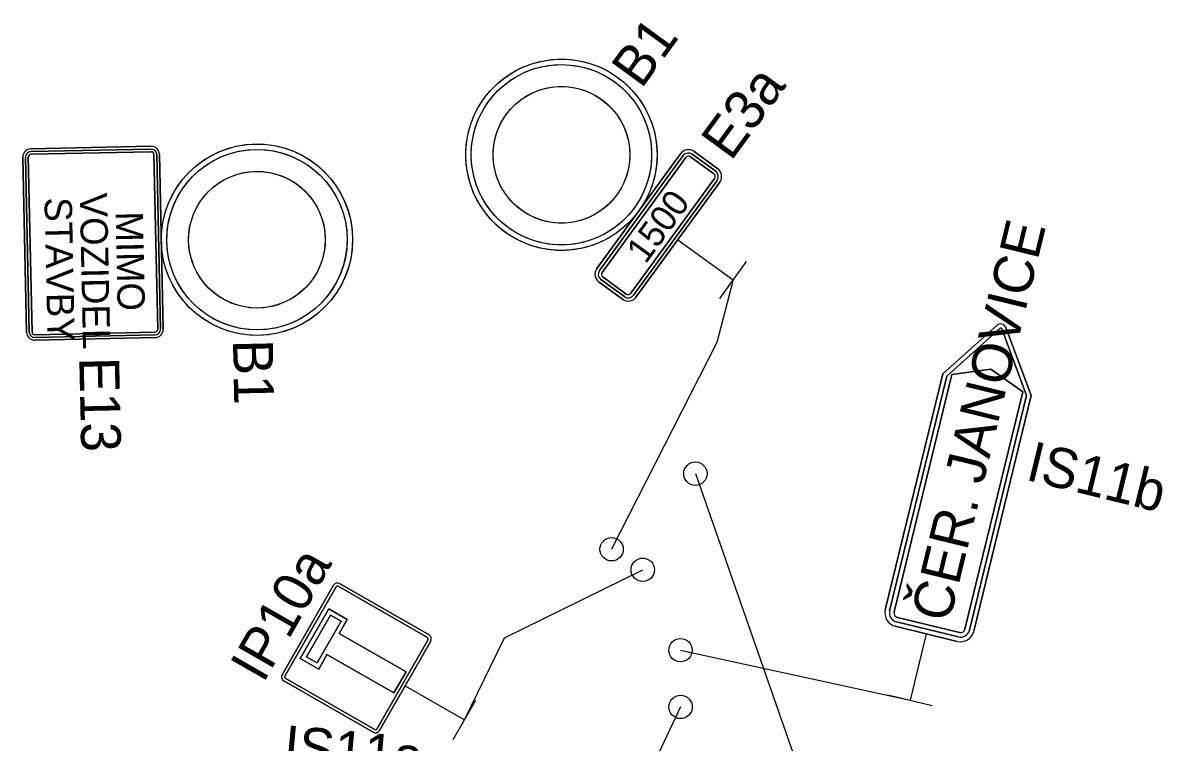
# Model space of a CAD drawing. Extents: x -688893 to -679983, y -1088371 to -1075771.
# Drawn here: x -685301 to -683799, y -1081610 to -1080663 of the extents above; entities that cross this region are included whole.
import ezdxf

# ---------------------------------------------------------------- set-up
doc = ezdxf.new("R2010")
doc.units = 0
for name, color, linetype in [('SDZ', 7, 'Continuous'), ('SDZ ozn', 7, 'Continuous'), ('SDZ plochy', 7, 'Continuous'), ('SDZ symbol', 7, 'Continuous'), ('SDZ text', 7, 'Continuous')]:
    doc.layers.add(name, color=color, linetype=linetype)

msp = doc.modelspace()

# ---------------------------------------------------------------- linework, layer by layer
at = {"layer": 'SDZ'}
for p, q in [((-685290.3, -1080828.6), (-685131.9, -1080825.2)), ((-685290.3, -1080828.6), (-685290.3, -1080828.6)), ((-685290.2, -1080832.2), (-685131.8, -1080828.8)), ((-685295.9, -1081069.9), (-685300.8, -1080839.6)), ((-685292.3, -1081069.8), (-685297.2, -1080839.5)), ((-685293.6, -1080839.4), (-685288.7, -1081069.8)), ((-685131.8, -1080832.4), (-685290.1, -1080835.8)), ((-685123.2, -1081066.2), (-685128.1, -1080835.9)), ((-685124.5, -1080835.8), (-685119.6, -1081066.2)), ((-685120.9, -1080835.7), (-685116, -1081066.1)), ((-684438.2, -1080948.2), (-684365.5, -1081001.2)), ((-684383.2, -1081025.5), (-684347.8, -1080977)), ((-685285, -1081073.3), (-685126.7, -1081069.9)), ((-684089.5, -1081124.8), (-684018.3, -1081061.1)), ((-684014.1, -1081065), (-684084.1, -1081128)), ((-684018.4, -1081061.2), (-684018.4, -1081061.2)), ((-683979.2, -1081153.5), (-684011.7, -1081065.6)), ((-684006.3, -1081064), (-683972.9, -1081153.2)), ((-685126.6, -1081073.5), (-685285, -1081076.9)), ((-685126.5, -1081077.1), (-685284.9, -1081080.5)), ((-684165.2, -1081435.5), (-684089.5, -1081124.8)), ((-684084.1, -1081128), (-684159.4, -1081436.9)), ((-684153.5, -1081438.4), (-684077.4, -1081125.9)), ((-684077.4, -1081125.9), (-684026.2, -1081118.6)), ((-684026.2, -1081118.6), (-683984.2, -1081148.6)), ((-683984.2, -1081148.6), (-684060.3, -1081461.1)), ((-684054.4, -1081462.5), (-683979.2, -1081153.5)), ((-683972.9, -1081153.2), (-684048.6, -1081463.9)), ((-684415.2, -1081256.3), (-683939.8, -1082615.4)), ((-684959.3, -1081521.1), (-684891.8, -1081403.3)), ((-684959.3, -1081521.1), (-684891.8, -1081403.3)), ((-684955.9, -1081523.1), (-684888.3, -1081405.3)), ((-684955.9, -1081523.1), (-684888.3, -1081405.3)), ((-684885.7, -1081404.5), (-684767.8, -1081472.1)), ((-684885.7, -1081404.5), (-684767.8, -1081472.1)), ((-684883.7, -1081401.1), (-684765.9, -1081468.7)), ((-684883.7, -1081401.1), (-684765.9, -1081468.7)), ((-684935.4, -1081499.7), (-684898, -1081434.4)), ((-684935.4, -1081499.7), (-684898, -1081434.4)), ((-684927.4, -1081497.5), (-684895.8, -1081442.5)), ((-684927.4, -1081497.5), (-684895.8, -1081442.5)), ((-684898, -1081434.4), (-684873.8, -1081448.3)), ((-684898, -1081434.4), (-684873.8, -1081448.3)), ((-684895.8, -1081442.5), (-684881.8, -1081450.5)), ((-684895.8, -1081442.5), (-684881.8, -1081450.5)), ((-684881.8, -1081450.5), (-684913.4, -1081505.5)), ((-684881.8, -1081450.5), (-684913.4, -1081505.5)), ((-684873.8, -1081448.3), (-684884.3, -1081466.6)), ((-684873.8, -1081448.3), (-684884.3, -1081466.6)), ((-684070.4, -1081477.2), (-684152, -1081457.3)), ((-684150.6, -1081451.4), (-684068.9, -1081471.3)), ((-684067.5, -1081465.5), (-684149.1, -1081445.6)), ((-684884.3, -1081466.6), (-684796.1, -1081517.1)), ((-684884.3, -1081466.6), (-684796.1, -1081517.1)), ((-684767.1, -1081474.8), (-684834.7, -1081592.6)), ((-684767.1, -1081474.8), (-684834.7, -1081592.6)), ((-684111.2, -1081467.2), (-684132.5, -1081554.7)), ((-684763.7, -1081476.7), (-684831.2, -1081594.6)), ((-684763.7, -1081476.7), (-684831.2, -1081594.6)), ((-684911.2, -1081513.6), (-684935.4, -1081499.7)), ((-684911.2, -1081513.6), (-684935.4, -1081499.7)), ((-684913.4, -1081505.5), (-684927.4, -1081497.5)), ((-684913.4, -1081505.5), (-684927.4, -1081497.5)), ((-684900.3, -1081494.6), (-684911.2, -1081513.6)), ((-684900.3, -1081494.6), (-684911.2, -1081513.6)), ((-684812.2, -1081545.1), (-684900.3, -1081494.6)), ((-684812.2, -1081545.1), (-684900.3, -1081494.6)), ((-684796.1, -1081517.1), (-684812.2, -1081545.1)), ((-684796.1, -1081517.1), (-684812.2, -1081545.1)), ((-684839.3, -1081596.8), (-684957.1, -1081529.2)), ((-684839.3, -1081596.8), (-684957.1, -1081529.2)), ((-684837.3, -1081593.4), (-684955.2, -1081525.8)), ((-684837.3, -1081593.4), (-684955.2, -1081525.8)), ((-684797.5, -1081535.7), (-684719.4, -1081580.4)), ((-684161.6, -1081547.6), (-684103.3, -1081561.8)), ((-684734.3, -1081606.5), (-684704.5, -1081554.4))]:
    msp.add_line(p, q, dxfattribs=at)
for points in [[(-684544.9, -1080986.2), (-684434.6, -1080835)], [(-684541.5, -1080988.7), (-684431.2, -1080837.5)], [(-684538.1, -1080991.3), (-684427.7, -1080840)], [(-684421.8, -1080839), (-684390.8, -1080861.6)], [(-684419.3, -1080835.6), (-684388.3, -1080858.2)], [(-684416.8, -1080832.2), (-684385.8, -1080854.7)], [(-684389.9, -1080867.5), (-684500.2, -1081018.8)], [(-684386.5, -1080870.1), (-684496.8, -1081021.3)], [(-684383, -1080872.6), (-684493.4, -1081023.9)], [(-684511.2, -1081026.6), (-684542.1, -1081004.1)], [(-684508.7, -1081023.2), (-684539.6, -1081000.6)], [(-684506.2, -1081019.8), (-684537.1, -1080997.2)], [(-684365.5, -1081001.2), (-684386.9, -1081083.8), (-684525.5, -1081355.9)], [(-684719.4, -1081580.4), (-684666.5, -1081472.6), (-684484.5, -1081382.9)], [(-684434.8, -1081488.7), (-684132.5, -1081554.7)], [(-684434.7, -1081563.5), (-684738.1, -1082207.5), (-684913.1, -1082202.6)]]:
    msp.add_lwpolyline(points, dxfattribs=at)
for centre in [(-684415.2, -1081256.3), (-684525.5, -1081355.9), (-684484.5, -1081382.9), (-684434.8, -1081488.7), (-684434.7, -1081563.5)]:
    msp.add_circle(centre, 15.4, dxfattribs=at)
for centre, radius, start, end in [((-684424.3, -1080842.5), 12.8, 53.8996, 143.8996), ((-684424.3, -1080842.5), 8.51, 53.8996, 143.8996), ((-684424.3, -1080842.5), 4.26, 53.8996, 143.8996), ((-684393.4, -1080865), 8.51, 323.8996, 53.8996), ((-684393.4, -1080865), 12.8, 323.8996, 53.8996), ((-684393.4, -1080865), 4.26, 323.8996, 53.8996), ((-684534.6, -1080993.8), 12.8, 143.8996, 233.8996), ((-684534.6, -1080993.8), 8.51, 143.8996, 233.8996), ((-684534.6, -1080993.8), 4.26, 143.8996, 233.8996), ((-684503.7, -1081016.3), 12.8, 233.8996, 323.8996), ((-684503.7, -1081016.3), 8.51, 233.8996, 323.8996), ((-684503.7, -1081016.3), 4.26, 233.8996, 323.8996), ((-684013.3, -1081066.7), 7.5, 20.5019, 131.8201), ((-684013.1, -1081066.1), 1.5, 20.3066, 132.0094), ((-684886.6, -1081406.2), 5.91, 60.1689, 150.1689), ((-684886.6, -1081406.2), 1.97, 60.1689, 150.1689), ((-684147.7, -1081439.8), 18, 166.3101, 256.3101), ((-684147.7, -1081439.8), 12, 166.3101, 256.3101), ((-684147.7, -1081439.8), 6, 166.3101, 256.3101), ((-684768.8, -1081473.8), 1.97, 330.1689, 60.1689), ((-684768.8, -1081473.8), 5.91, 330.1689, 60.1689), ((-684066.1, -1081459.7), 18, 256.3101, 346.3101), ((-684066.1, -1081459.7), 12, 256.3101, 346.3101), ((-684066.1, -1081459.7), 6, 256.3101, 346.3101), ((-684954.2, -1081524.1), 5.91, 150.1689, 240.1689), ((-684954.2, -1081524.1), 1.97, 150.1689, 240.1689), ((-684836.4, -1081591.7), 5.91, 240.1689, 330.1689), ((-684836.4, -1081591.7), 1.97, 240.1689, 330.1689)]:
    msp.add_arc(centre, radius, start, end, dxfattribs=at)
for centre, major_axis in [((-684591.6, -1080836.4), (93.3, 84.7)), ((-684591.6, -1080836.4), (88, 79.8)), ((-684591.6, -1080836.4), (66.6, 60.5)), ((-684992.5, -1080948.2), (-22.8, -123.9)), ((-684992.5, -1080948.2), (-21.5, -116.8)), ((-684992.5, -1080948.2), (-16.3, -88.5))]:
    msp.add_ellipse(centre, major_axis=major_axis, ratio=0.999898, dxfattribs=at)
at = {"layer": 'SDZ plochy'}
for p, q in [((-685131.9, -1080825.2), (-685290.3, -1080828.6)), ((-685131.8, -1080828.8), (-685290.2, -1080832.2)), ((-685290.2, -1080832.2), (-685131.8, -1080828.8)), ((-685300.8, -1080839.6), (-685295.9, -1081069.9)), ((-685297.2, -1080839.5), (-685292.3, -1081069.8)), ((-685292.3, -1081069.8), (-685297.2, -1080839.5)), ((-685288.7, -1081069.8), (-685293.6, -1080839.4)), ((-685293.6, -1080839.4), (-685288.7, -1081069.8)), ((-685290.1, -1080835.8), (-685131.8, -1080832.4)), ((-685131.8, -1080832.4), (-685290.1, -1080835.8)), ((-685128.1, -1080835.9), (-685123.2, -1081066.2)), ((-685123.2, -1081066.2), (-685128.1, -1080835.9)), ((-685119.6, -1081066.2), (-685124.5, -1080835.8)), ((-685124.5, -1080835.8), (-685119.6, -1081066.2)), ((-685116, -1081066.1), (-685120.9, -1080835.7)), ((-684434.6, -1080835), (-684544.9, -1080986.2)), ((-684541.5, -1080988.7), (-684431.2, -1080837.5)), ((-684431.2, -1080837.5), (-684541.5, -1080988.7)), ((-684538.1, -1080991.3), (-684427.7, -1080840)), ((-684427.7, -1080840), (-684538.1, -1080991.3)), ((-684421.8, -1080839), (-684390.8, -1080861.6)), ((-684390.8, -1080861.6), (-684421.8, -1080839)), ((-684419.3, -1080835.6), (-684388.3, -1080858.2)), ((-684388.3, -1080858.2), (-684419.3, -1080835.6)), ((-684385.8, -1080854.7), (-684416.8, -1080832.2)), ((-684389.9, -1080867.5), (-684500.2, -1081018.8)), ((-684500.2, -1081018.8), (-684389.9, -1080867.5)), ((-684386.5, -1080870.1), (-684496.8, -1081021.3)), ((-684496.8, -1081021.3), (-684386.5, -1080870.1)), ((-684493.4, -1081023.9), (-684383, -1080872.6)), ((-684542.1, -1081004.1), (-684511.2, -1081026.6)), ((-684508.7, -1081023.2), (-684539.6, -1081000.6)), ((-684539.6, -1081000.6), (-684508.7, -1081023.2)), ((-684506.2, -1081019.8), (-684537.1, -1080997.2)), ((-684537.1, -1080997.2), (-684506.2, -1081019.8)), ((-685126.7, -1081069.9), (-685285, -1081073.3)), ((-685285, -1081073.3), (-685126.7, -1081069.9)), ((-684018.3, -1081061.1), (-684089.5, -1081124.8)), ((-684084.1, -1081128), (-684014.1, -1081065)), ((-684014.1, -1081065), (-684084.1, -1081128)), ((-684011.7, -1081065.6), (-683979.2, -1081153.5)), ((-683979.2, -1081153.5), (-684011.7, -1081065.6)), ((-683972.9, -1081153.2), (-684006.3, -1081064)), ((-685285, -1081076.9), (-685126.6, -1081073.5)), ((-685126.6, -1081073.5), (-685285, -1081076.9)), ((-685284.9, -1081080.5), (-685126.5, -1081077.1)), ((-684089.5, -1081124.8), (-684165.2, -1081435.5)), ((-684159.4, -1081436.9), (-684084.1, -1081128)), ((-684084.1, -1081128), (-684159.4, -1081436.9)), ((-684077.4, -1081125.9), (-684153.5, -1081438.4)), ((-684153.5, -1081438.4), (-684077.4, -1081125.9)), ((-684026.2, -1081118.6), (-684077.4, -1081125.9)), ((-684077.4, -1081125.9), (-684026.2, -1081118.6)), ((-683984.2, -1081148.6), (-684026.2, -1081118.6)), ((-684026.2, -1081118.6), (-683984.2, -1081148.6)), ((-684060.3, -1081461.1), (-683984.2, -1081148.6)), ((-683984.2, -1081148.6), (-684060.3, -1081461.1)), ((-683979.2, -1081153.5), (-684054.4, -1081462.5)), ((-684054.4, -1081462.5), (-683979.2, -1081153.5)), ((-684048.6, -1081463.9), (-683972.9, -1081153.2)), ((-684891.8, -1081403.3), (-684959.3, -1081521.1)), ((-684888.3, -1081405.3), (-684955.9, -1081523.1)), ((-684955.9, -1081523.1), (-684888.3, -1081405.3)), ((-684767.8, -1081472.1), (-684885.7, -1081404.5)), ((-684885.7, -1081404.5), (-684767.8, -1081472.1)), ((-684765.9, -1081468.7), (-684883.7, -1081401.1)), ((-684935.4, -1081499.7), (-684898, -1081434.4)), ((-684898, -1081434.4), (-684935.4, -1081499.7)), ((-684895.8, -1081442.5), (-684927.4, -1081497.5)), ((-684927.4, -1081497.5), (-684895.8, -1081442.5)), ((-684898, -1081434.4), (-684873.8, -1081448.3)), ((-684873.8, -1081448.3), (-684898, -1081434.4)), ((-684881.8, -1081450.5), (-684895.8, -1081442.5)), ((-684895.8, -1081442.5), (-684881.8, -1081450.5)), ((-684913.4, -1081505.5), (-684881.8, -1081450.5)), ((-684881.8, -1081450.5), (-684913.4, -1081505.5)), ((-684873.8, -1081448.3), (-684884.3, -1081466.6)), ((-684884.3, -1081466.6), (-684873.8, -1081448.3)), ((-684152, -1081457.3), (-684070.4, -1081477.2)), ((-684068.9, -1081471.3), (-684150.6, -1081451.4)), ((-684150.6, -1081451.4), (-684068.9, -1081471.3)), ((-684149.1, -1081445.6), (-684067.5, -1081465.5)), ((-684067.5, -1081465.5), (-684149.1, -1081445.6)), ((-684884.3, -1081466.6), (-684796.1, -1081517.1)), ((-684796.1, -1081517.1), (-684884.3, -1081466.6)), ((-684834.7, -1081592.6), (-684767.1, -1081474.8)), ((-684767.1, -1081474.8), (-684834.7, -1081592.6)), ((-684831.2, -1081594.6), (-684763.7, -1081476.7)), ((-684911.2, -1081513.6), (-684935.4, -1081499.7)), ((-684935.4, -1081499.7), (-684911.2, -1081513.6)), ((-684927.4, -1081497.5), (-684913.4, -1081505.5)), ((-684913.4, -1081505.5), (-684927.4, -1081497.5)), ((-684900.3, -1081494.6), (-684911.2, -1081513.6)), ((-684911.2, -1081513.6), (-684900.3, -1081494.6)), ((-684812.2, -1081545.1), (-684900.3, -1081494.6)), ((-684900.3, -1081494.6), (-684812.2, -1081545.1)), ((-684796.1, -1081517.1), (-684812.2, -1081545.1)), ((-684812.2, -1081545.1), (-684796.1, -1081517.1)), ((-684957.1, -1081529.2), (-684839.3, -1081596.8)), ((-684955.2, -1081525.8), (-684837.3, -1081593.4)), ((-684837.3, -1081593.4), (-684955.2, -1081525.8))]:
    msp.add_line(p, q, dxfattribs=at)
for centre, radius in [((-684591.6, -1080836.4), 126), ((-684591.6, -1080836.4), 118.8), ((-684591.6, -1080836.4), 118.8), ((-684591.6, -1080836.4), 90), ((-684591.6, -1080836.4), 90), ((-684992.5, -1080948.2), 126), ((-684992.5, -1080948.2), 118.8), ((-684992.5, -1080948.2), 118.8), ((-684992.5, -1080948.2), 90), ((-684992.5, -1080948.2), 90)]:
    msp.add_circle(centre, radius, dxfattribs=at)
for centre, radius, start, end in [((-685290, -1080839.4), 10.8, 91.2233, 181.2233), ((-685131.7, -1080836), 10.8, 1.2233, 91.2233), ((-685131.7, -1080836), 7.2, 1.2233, 91.2233), ((-685131.7, -1080836), 7.2, 1.2233, 91.2233), ((-684424.3, -1080842.5), 12.8, 53.8996, 143.8996), ((-685290, -1080839.4), 7.2, 91.2233, 181.2233), ((-685290, -1080839.4), 7.2, 91.2233, 181.2233), ((-685290, -1080839.4), 3.6, 91.2233, 181.2233), ((-685290, -1080839.4), 3.6, 91.2233, 181.2233), ((-685131.7, -1080836), 3.6, 1.2233, 91.2233), ((-685131.7, -1080836), 3.6, 1.2233, 91.2233), ((-684424.3, -1080842.5), 8.51, 53.8996, 143.8996), ((-684424.3, -1080842.5), 8.51, 53.8996, 143.8996), ((-684424.3, -1080842.5), 4.26, 53.8996, 143.8996), ((-684424.3, -1080842.5), 4.26, 53.8996, 143.8996), ((-684393.4, -1080865), 8.51, 323.8996, 53.8996), ((-684393.4, -1080865), 8.51, 323.8996, 53.8996), ((-684393.4, -1080865), 12.8, 323.8996, 53.8996), ((-684393.4, -1080865), 4.26, 323.8996, 53.8996), ((-684393.4, -1080865), 4.26, 323.8996, 53.8996), ((-684534.6, -1080993.8), 12.8, 143.8996, 233.8996), ((-684534.6, -1080993.8), 8.51, 143.8996, 233.8996), ((-684534.6, -1080993.8), 8.51, 143.8996, 233.8996), ((-684534.6, -1080993.8), 4.26, 143.8996, 233.8996), ((-684534.6, -1080993.8), 4.26, 143.8996, 233.8996), ((-684503.7, -1081016.3), 12.8, 233.8996, 323.8996), ((-684503.7, -1081016.3), 8.51, 233.8996, 323.8996), ((-684503.7, -1081016.3), 8.51, 233.8996, 323.8996), ((-684503.7, -1081016.3), 4.26, 233.8996, 323.8996), ((-684503.7, -1081016.3), 4.26, 233.8996, 323.8996), ((-685285.1, -1081069.7), 10.8, 181.2233, 271.2233), ((-685285.1, -1081069.7), 7.2, 181.2233, 271.2233), ((-685285.1, -1081069.7), 7.2, 181.2233, 271.2233), ((-685285.1, -1081069.7), 3.6, 181.2233, 271.2233), ((-685285.1, -1081069.7), 3.6, 181.2233, 271.2233), ((-685126.8, -1081066.3), 3.6, 271.2233, 1.2233), ((-685126.8, -1081066.3), 3.6, 271.2233, 1.2233), ((-685126.8, -1081066.3), 7.2, 271.2233, 1.2233), ((-685126.8, -1081066.3), 7.2, 271.2233, 1.2233), ((-685126.8, -1081066.3), 10.8, 271.2233, 1.2233), ((-684013.3, -1081066.7), 7.5, 20.5019, 131.8201), ((-684013.1, -1081066.1), 1.5, 20.3066, 132.0094), ((-684013.1, -1081066.1), 1.5, 20.3066, 132.0094), ((-684886.6, -1081406.2), 5.91, 60.1689, 150.1689), ((-684886.6, -1081406.2), 1.97, 60.1689, 150.1689), ((-684886.6, -1081406.2), 1.97, 60.1689, 150.1689), ((-684147.7, -1081439.8), 18, 166.3101, 256.3101), ((-684147.7, -1081439.8), 12, 166.3101, 256.3101), ((-684147.7, -1081439.8), 12, 166.3101, 256.3101), ((-684147.7, -1081439.8), 6, 166.3101, 256.3101), ((-684147.7, -1081439.8), 6, 166.3101, 256.3101), ((-684768.8, -1081473.8), 1.97, 330.1689, 60.1689), ((-684768.8, -1081473.8), 1.97, 330.1689, 60.1689), ((-684768.8, -1081473.8), 5.91, 330.1689, 60.1689), ((-684066.1, -1081459.7), 18, 256.3101, 346.3101), ((-684066.1, -1081459.7), 12, 256.3101, 346.3101), ((-684066.1, -1081459.7), 12, 256.3101, 346.3101), ((-684066.1, -1081459.7), 6, 256.3101, 346.3101), ((-684066.1, -1081459.7), 6, 256.3101, 346.3101), ((-684954.2, -1081524.1), 5.91, 150.1689, 240.1689), ((-684954.2, -1081524.1), 1.97, 150.1689, 240.1689), ((-684954.2, -1081524.1), 1.97, 150.1689, 240.1689), ((-684836.4, -1081591.7), 5.91, 240.1689, 330.1689), ((-684836.4, -1081591.7), 1.97, 240.1689, 330.1689), ((-684836.4, -1081591.7), 1.97, 240.1689, 330.1689)]:
    msp.add_arc(centre, radius, start, end, dxfattribs=at)
at = {"layer": 'SDZ text'}
for centre, radius, start, end in [((-685290, -1080839.4), 10.8, 91.2233, 181.2233), ((-685131.7, -1080836), 10.8, 1.2233, 91.2233), ((-685131.7, -1080836), 7.2, 1.2233, 91.2233), ((-685290, -1080839.4), 7.2, 91.2233, 181.2233), ((-685290, -1080839.4), 3.6, 91.2233, 181.2233), ((-685131.7, -1080836), 3.6, 1.2233, 91.2233), ((-685285.1, -1081069.7), 10.8, 181.2233, 271.2233), ((-685285.1, -1081069.7), 7.2, 181.2233, 271.2233), ((-685285.1, -1081069.7), 3.6, 181.2233, 271.2233), ((-685126.8, -1081066.3), 3.6, 271.2233, 1.2233), ((-685126.8, -1081066.3), 7.2, 271.2233, 1.2233), ((-685126.8, -1081066.3), 10.8, 271.2233, 1.2233)]:
    msp.add_arc(centre, radius, start, end, dxfattribs=at)

# ---------------------------------------------------------------- texts
at = {"layer": 'SDZ'}
for s, rotation, p in [('B1', 53.8996, (-684486.4, -1080750.7)), ('B1', 271.2231, (-685024.2, -1081080.1)), ('E13', 271.2231, (-685226.5, -1081103.3))]:
    msp.add_text(s, height=52.5, rotation=rotation, dxfattribs=at).set_placement(p)
at = {"layer": 'SDZ ozn'}
for s, rotation, p in [('E3a', 53.7833, (-684368.4, -1080845.9)), ('IS11b', 346.3101, (-683981.9, -1081264.1)), ('IP10a', 60.1689, (-684984.2, -1081533.4)), ('IS11a', 354.707, (-684959, -1081639.7))]:
    msp.add_text(s, height=52.5, rotation=rotation, dxfattribs=at).set_placement(p)
at = {"layer": 'SDZ symbol'}
for s, height, rotation, p in [('VOZIDEL', 36, 271.2233, (-685225.9, -1080886.8)), ('1500', 34.04, 53.8996, (-684480.7, -1080981.2)), ('STAVBY', 36, 271.2233, (-685272.3, -1080892.8)), ('MIMO', 36, 271.2233, (-685178.7, -1080911.4)), ('ČER. JANOVICE', 52.5, 76.3101, (-684080.9, -1081453.8))]:
    msp.add_text(s, height=height, rotation=rotation, dxfattribs=at).set_placement(p)

doc.saveas('drawing.dxf')
